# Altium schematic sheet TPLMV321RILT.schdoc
size 127 x 101 mm
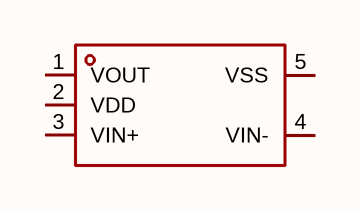
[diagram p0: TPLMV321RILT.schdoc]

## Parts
U?  tplmv321rilt  [SOT-23-5_L3.0-W1.7-P0.95-LS2.8-BR]  (value not drawn)

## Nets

Not connected (* = marked no-connect by the designer): U? 1(VOUT) 2(VDD) 3(VIN+) 4(VIN-) 5(VSS)

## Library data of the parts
U? = tplmv321rilt: 放大器数:1;轨到轨:轨到轨输入,轨到轨输出;增益带宽积(GBW):1MHz;输入失调电压(Vos):5mV;压摆率(SR):600V/ms;输入偏置电流(Ib):10pA;; Manufacturer: TECH PUBLIC(台舟); AddInBom: yes; ModelId: 0a2a1b8f50944f73965918ad6e5fe167; ModelName: SOT-23-5_L2.9-W1.6-H1.1-LS2.8-P0.95; ModelTransform: 114.173,109.636,0,180,0,0,0,0,0; Number of Channels: 1; Maximum Power Supply Range (Vdd-Vss): 5.5V; Gain Bandwidth Product: 1MHz; Vos - Input Offset Voltage: 5mV; Input Offset Voltage Drift(Vos TC): 2uV/℃; Ib - Input Bias Current: 10pA; Input Voltage Noise Density: 20nV/√Hz@10kHz; Common Mode Rejection Ratio(CMRR): 80dB; Quiescent Current: 40uA; Output Current: 20mA; Single supply: 2.2V~5.5V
